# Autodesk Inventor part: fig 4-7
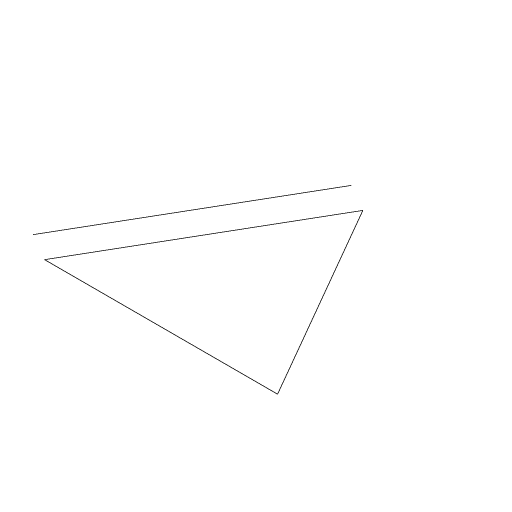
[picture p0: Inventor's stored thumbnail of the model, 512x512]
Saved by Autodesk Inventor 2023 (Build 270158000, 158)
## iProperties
Created: 2005-02
Part Number: fig 4-7
Document SubType Name: Modeling
Designer: CADCIM
Manufacturer: Standard
Standards Organization: Custom
Density: 1 g/cm^3
Material: Generic
Appearance: Default
Author: CADCIM
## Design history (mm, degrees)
sketch "Sketch1"
  geometry: L1 (-3.883, 28.419)-(-24.946, -8.063); L2 (-24.946, -8.063)-(17.18, -8.063); L3 (17.18, -8.063)-(-3.883, 28.419); L4 (-8.847, 31.285)-(-29.909, -5.197)
  constraints: 8 end point, 2 equal length, 1 horizontal, 1 parallel, 1 other
